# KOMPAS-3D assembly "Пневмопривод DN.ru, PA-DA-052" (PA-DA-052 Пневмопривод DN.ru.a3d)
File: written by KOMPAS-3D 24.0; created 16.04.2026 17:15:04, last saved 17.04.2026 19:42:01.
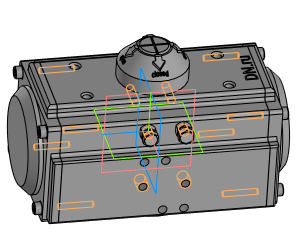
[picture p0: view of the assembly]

Document properties: Автор: DN.ru; Полное имя файла: C:\Работа\PA-DA-х Пневмопривод DN.ru\052\исходные материалы\PA-DA-052 Пневмопривод DN.ru.a3d

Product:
- Component [detail]: Пневмопривод DN.ru  | designation PA-DA-052  | qty 1  | pos. 1  | Масса: 1.4; Раздел спецификации: Прочие изделия; Примечание: D290-00293; Автор: DN.ru; source file: PA-DA-052 Пневмопривод DN.ru.m3d
- Component [standard]: Винт М4-6gx30 ГОСТ 11738-84  | qty 8  | pos. 2  | Масса: 0.00361; Раздел спецификации: Стандартные изделия; Рассекать на разрезах: no
- Component [standard]: Болт М5-6gx50 ГОСТ 7805-70  | qty 2  | pos. 3  | Масса: 0.008999; Раздел спецификации: Стандартные изделия; Рассекать на разрезах: no
- Component [standard]: Гайка М5-6H ГОСТ 5915-70  | qty 2  | pos. 4  | Масса: 0.00144; Раздел спецификации: Стандартные изделия; Рассекать на разрезах: no
- Part/product: Пневмопривод DN.ru  | designation PA-DA-052
    Масса: 1.4
    Раздел спецификации: Прочие изделия
    Примечание: D290-00293

Referenced files in C:\Работа\PA-DA-х Пневмопривод DN.ru\052\исходные материалы\: PA-DA-052 Пневмопривод DN.ru.m3d
Referenced files in C:\Program Files\ASCON\KOMPAS-3D v24\Libs\PolynomLib\DATA\vault\Methods\Kompas\3D\: PLib_Screw_GOST_11738_1500.m3d, PLib_Bolt_1_900.m3d, PLib_Nut_OST92_900.m3d
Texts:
  BOSimple***PART:1ff84fa3-e62c-5a6d-126f-35e3f1af4542***SHORTLOC:Root±30±20±10±80±10±GMC90[Нет;Без покрытия;Без указания материала;0,7;-;30;4]
  BOSimple***PART:53acba15-081d-1c02-6810-072b309dd366***SHORTLOC:Root±30±20±10±80±10±©{}30±©{BASE}130±30[Нет;Без покрытия;Без указания материала;50;5;8;0,8;-]
  BOSimple***PART:0338bb82-6b79-df62-da33-8b23172f1b3e***SHORTLOC:Root±30±10±20±©{}110±10±50±60[Нет;Без покрытия;Без указания материала;-;5;0,8;8]
  PA-DA-052
  PA-DA-052  Пневмопривод DN.ru
  Винт М4-6gx30 ГОСТ 11738-84 (1)
  Винт М4-6gx30 ГОСТ 11738-84 (2)
  Винт М4-6gx30 ГОСТ 11738-84 (3)
  Винт М4-6gx30 ГОСТ 11738-84 (4)
  Винт М4-6gx30 ГОСТ 11738-84 (5)
  Винт М4-6gx30 ГОСТ 11738-84 (6)
  Винт М4-6gx30 ГОСТ 11738-84 (7)
  Винт М4-6gx30 ГОСТ 11738-84 (8)
  Болт М5-6gx50 ГОСТ 7805-70 (1)
  hole1
  hole2
  Болт М5-6gx50 ГОСТ 7805-70 (2)
  Гайка М5-6H ГОСТ 5915-70 (1)
  bcut1
  hcut1
  cut1
  Гайка М5-6H ГОСТ 5915-70 (2)
  Plane. Начало координат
